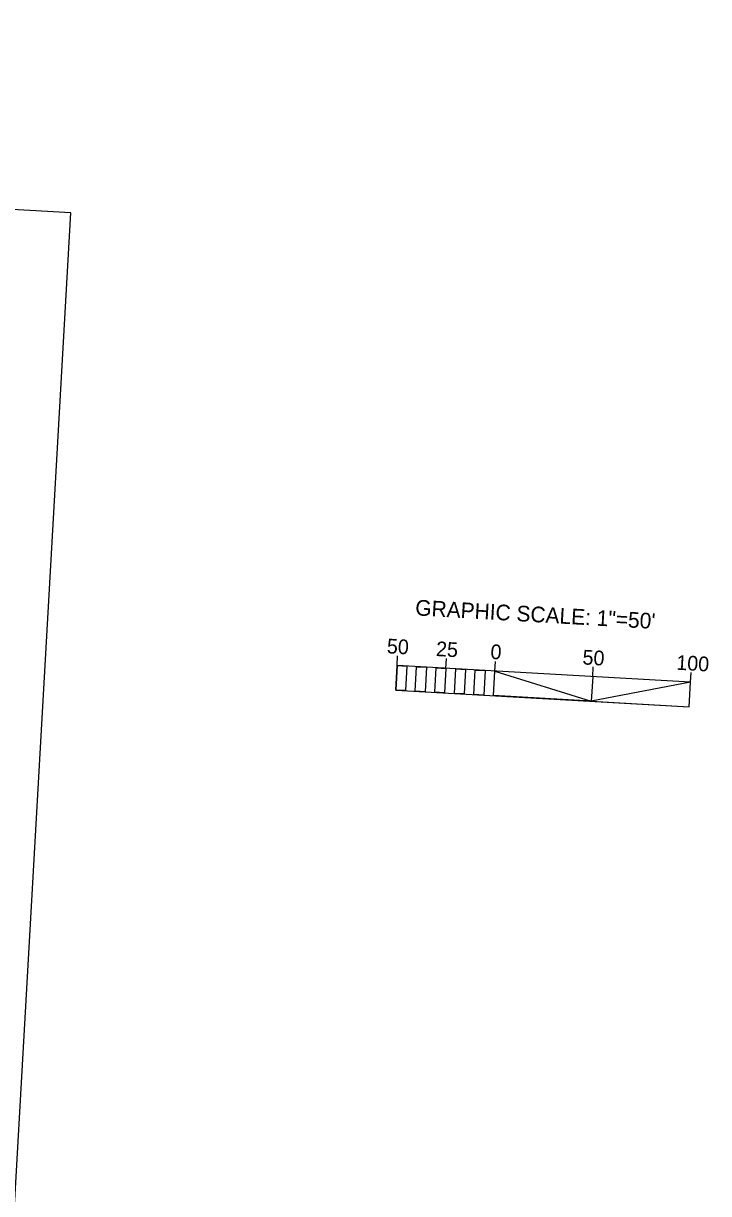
# Model space of a CAD drawing. Extents: x 2604316 to 2606605, y 617090 to 619543.
# Drawn here: x 2606051 to 2606401, y 618510 to 619107 of the extents above; entities that cross this region are included whole.
import ezdxf

# ---------------------------------------------------------------- set-up
doc = ezdxf.new("R2010")
doc.units = 0
doc.layers.add('Sheet Project Info Box CELL', color=7, linetype='Continuous')
doc.layers.add('Stewart Plot Border Xerox6279 and LJ5000', color=7, linetype='Continuous')

msp = doc.modelspace()

# ---------------------------------------------------------------- linework, layer by layer
at = {"layer": 'Sheet Project Info Box CELL'}
for p, q in [((2606241.93, 618779.51), (2606242.21, 618784.49)), ((2606241.94, 618779.53), (2606242.23, 618784.51)), ((2606241.93, 618779.51), (2606241.22, 618767.03)), ((2606241.93, 618779.51), (2606241.93, 618779.51)), ((2606391.69, 618770.98), (2606241.93, 618779.51)), ((2606266.89, 618778.08), (2606267.18, 618783.08)), ((2606266.9, 618778.09), (2606267.19, 618783.08)), ((2606291.85, 618776.66), (2606292.13, 618781.65)), ((2606341.77, 618773.83), (2606342.05, 618778.81)), ((2606341.78, 618773.84), (2606342.07, 618778.82)), ((2606276.87, 618777.52), (2606276.16, 618765.04)), ((2606341.77, 618773.83), (2606341.06, 618761.35)), ((2606391.69, 618770.98), (2606391.97, 618775.98)), ((2606391.7, 618770.98), (2606391.99, 618775.99)), ((2606241.22, 618767.03), (2606390.98, 618758.49)), ((2606390.98, 618758.49), (2606391.69, 618770.98))]:
    msp.add_line(p, q, dxfattribs=at)
for points in [[(2606241.93, 618779.51), (2606246.92, 618779.23), (2606246.21, 618766.75), (2606241.22, 618767.03)], [(2606251.91, 618778.95), (2606256.91, 618778.65), (2606256.2, 618766.17), (2606251.22, 618766.45)], [(2606261.9, 618778.36), (2606266.89, 618778.08), (2606266.18, 618765.61), (2606261.19, 618765.9)], [(2606271.88, 618777.8), (2606276.87, 618777.52), (2606276.16, 618765.04), (2606271.17, 618765.33)], [(2606281.87, 618777.24), (2606286.86, 618776.96), (2606286.15, 618764.46), (2606281.16, 618764.76)], [(2606291.85, 618776.66), (2606341.06, 618761.35), (2606291.14, 618764.18)], [(2606391.69, 618770.98), (2606341.06, 618761.35), (2606390.98, 618758.49)]]:
    msp.add_lwpolyline(points, close=True, dxfattribs=at)
at = {"layer": 'Stewart Plot Border Xerox6279 and LJ5000'}
msp.add_lwpolyline([(2604315.67, 618009.17), (2606012.92, 617912.5), (2606075.47, 619010.72), (2604378.22, 619107.39)], close=True, dxfattribs=at)

# ---------------------------------------------------------------- texts
at = {"layer": 'Sheet Project Info Box CELL'}
for s, height, p in [('GRAPHIC SCALE: 1"=50\'', 8, (2606251.04, 618805.19)), ('50', 7.5, (2606236.58, 618785.83)), ('25', 7.5, (2606261.66, 618784.41)), ('0', 7.5, (2606289.45, 618782.95)), ('50', 7.5, (2606336.42, 618780.14)), ('100', 7.5, (2606384.28, 618777.43))]:
    msp.add_text(s, height=height, rotation=356.74026, dxfattribs=at).set_placement(p)

doc.saveas('drawing.dxf')
